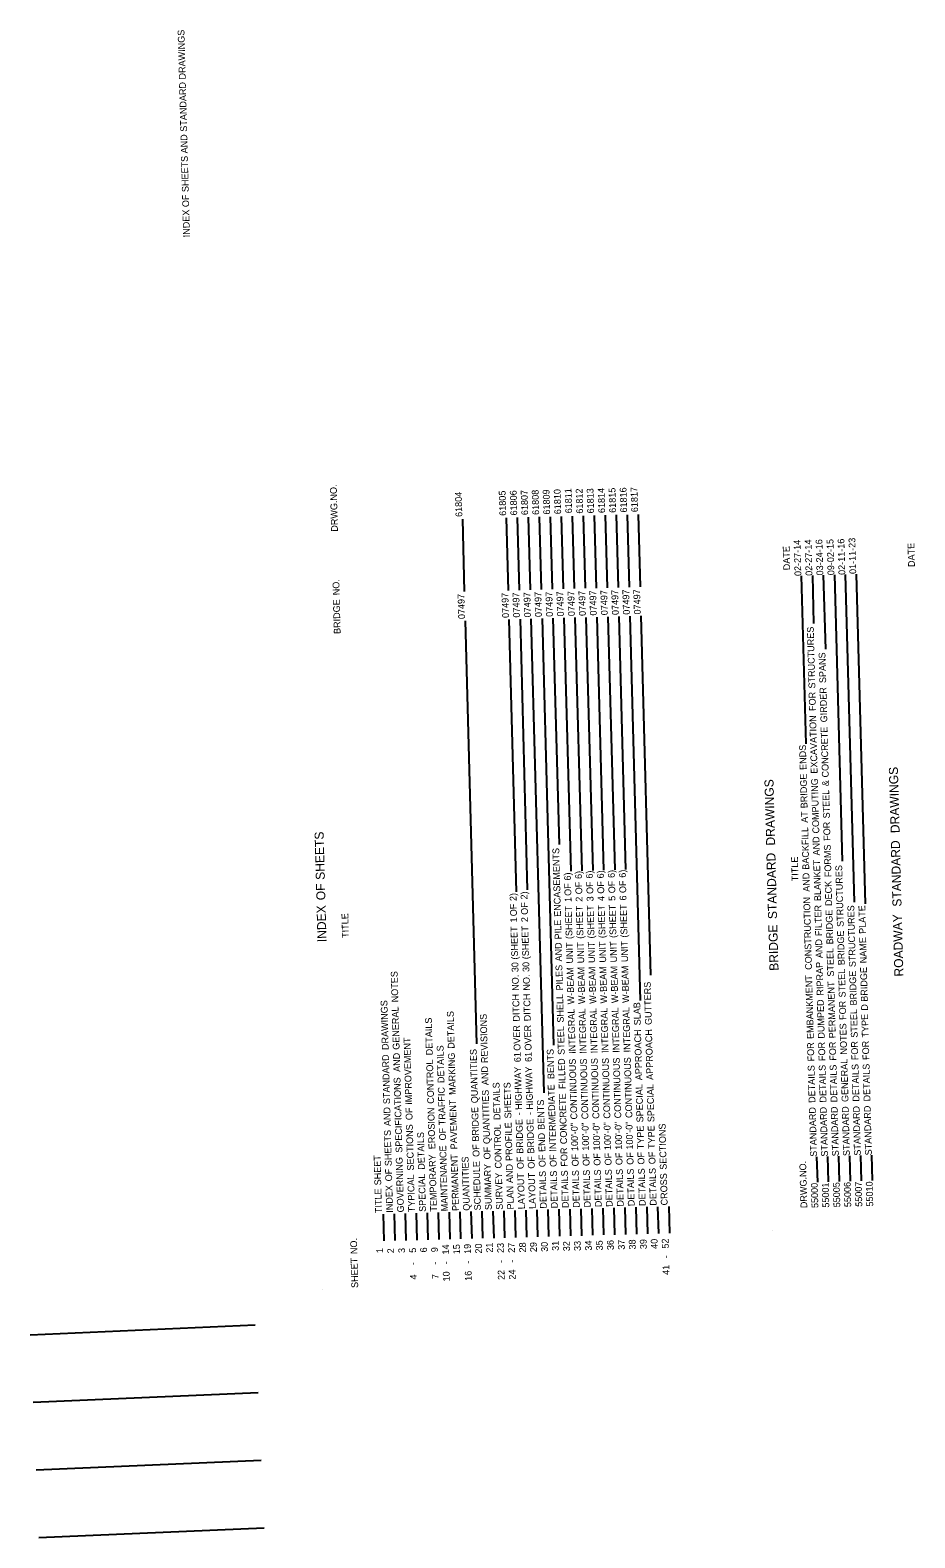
# Model space of a CAD drawing. Extents: x 1930579 to 1932146, y 596452 to 597806.
# Drawn here: x 1930579 to 1931365, y 596452 to 597789 of the extents above; entities that cross this region are included whole.
import ezdxf

# ---------------------------------------------------------------- set-up
doc = ezdxf.new("R2010")
doc.units = 0
for name, color, linetype in [('BR_Pr_Bent_CL', 7, 'Continuous'), ('Default', 7, 'Continuous'), ('R_Border', 7, 'Continuous')]:
    doc.layers.add(name, color=color, linetype=linetype)

msp = doc.modelspace()

# ---------------------------------------------------------------- linework, layer by layer
at = {"layer": 'BR_Pr_Bent_CL'}
for p, q in [((1930779.3, 596640.3), (1930579.5, 596631.6)), ((1930781.9, 596580.4), (1930582.1, 596571.7)), ((1930784.5, 596520.4), (1930584.7, 596511.8)), ((1930787.1, 596460.5), (1930587.3, 596451.8))]:
    msp.add_line(p, q, dxfattribs=at)
at = {"layer": 'Default'}
for p, q in [((1930963, 597355.3), (1930964.7, 597291)), ((1931002, 597356.4), (1931003.7, 597292)), ((1931011.7, 597356.6), (1931013.5, 597292.3)), ((1931021.5, 597356.9), (1931023.2, 597292.6)), ((1931031.2, 597357.2), (1931033, 597292.8)), ((1931041, 597357.4), (1931042.7, 597293.1)), ((1931050.7, 597357.7), (1931052.5, 597293.4)), ((1931060.5, 597357.9), (1931062.2, 597293.6)), ((1931070.2, 597358.2), (1931071.9, 597293.9)), ((1931080, 597358.5), (1931081.7, 597294.1)), ((1931089.7, 597358.7), (1931091.4, 597294.4)), ((1931099.5, 597359), (1931101.2, 597294.7)), ((1931109.2, 597359.2), (1931110.9, 597294.9)), ((1931119, 597359.5), (1931120.7, 597295.2)), ((1931263.8, 597305.1), (1931267.8, 597156.1)), ((1931273.6, 597305.4), (1931274.7, 597262.7)), ((1931283.3, 597305.7), (1931285.1, 597239.8)), ((1931293.1, 597305.9), (1931299.9, 597052)), ((1931302.8, 597306.2), (1931310.6, 597015.7)), ((1931312.5, 597306.4), (1931320.4, 597014.2)), ((1930965.4, 597265.2), (1930975.5, 596890)), ((1931004.4, 597266.3), (1931010.9, 597024.8)), ((1931014.2, 597266.6), (1931020.6, 597026.4)), ((1931023.9, 597266.8), (1931035.2, 596846.4)), ((1931033.7, 597267.1), (1931043.8, 596888.8)), ((1931043.4, 597267.3), (1931048.8, 597066.7)), ((1931053.1, 597267.6), (1931059.2, 597043.2)), ((1931062.9, 597267.9), (1931068.9, 597043.4)), ((1931072.6, 597268.1), (1931078.7, 597043.7)), ((1931082.4, 597268.4), (1931088.4, 597044)), ((1931092.1, 597268.6), (1931098.2, 597044.2)), ((1931101.9, 597268.9), (1931107.9, 597044.5)), ((1931111.6, 597269.2), (1931120.8, 596928.4)), ((1931121.4, 597269.4), (1931129.9, 596950.7)), ((1931278.3, 596767.3), (1931277.7, 596789.8)), ((1931288, 596767.5), (1931287.4, 596790)), ((1931297.7, 596767.8), (1931297.1, 596790.3)), ((1931307.5, 596768.1), (1931306.9, 596790.5)), ((1931317.2, 596768.3), (1931316.6, 596790.8)), ((1931327, 596768.6), (1931326.4, 596791.1)), ((1930893.6, 596715.1), (1930893, 596739)), ((1930903.4, 596715.4), (1930902.7, 596739.3)), ((1930913.1, 596715.6), (1930912.5, 596739.5)), ((1930922.9, 596715.9), (1930922.2, 596739.8)), ((1930932.6, 596716.2), (1930932, 596740)), ((1930942.3, 596716.4), (1930941.7, 596740.3)), ((1930952.1, 596716.7), (1930951.5, 596740.6)), ((1930961.8, 596717), (1930961.2, 596740.8)), ((1930971.6, 596717.2), (1930970.9, 596741.1)), ((1930981.3, 596717.5), (1930980.7, 596741.4)), ((1930991.1, 596717.7), (1930990.4, 596741.6)), ((1931000.8, 596718), (1931000.2, 596741.9)), ((1931010.6, 596718.3), (1931009.9, 596742.1)), ((1931020.3, 596718.5), (1931019.7, 596742.4)), ((1931030.1, 596718.8), (1931029.4, 596742.7)), ((1931039.8, 596719), (1931039.2, 596742.9)), ((1931049.6, 596719.3), (1931048.9, 596743.2)), ((1931059.3, 596719.6), (1931058.7, 596743.4)), ((1931069, 596719.8), (1931068.4, 596743.7)), ((1931078.8, 596720.1), (1931078.2, 596744)), ((1931088.5, 596720.4), (1931087.9, 596744.2)), ((1931098.3, 596720.6), (1931097.6, 596744.5)), ((1931108, 596720.9), (1931107.4, 596744.8)), ((1931117.8, 596721.1), (1931117.1, 596745)), ((1931127.5, 596721.4), (1931126.9, 596745.3)), ((1931137.3, 596721.7), (1931136.6, 596745.5)), ((1931147, 596721.9), (1931146.4, 596745.8)), ((1931238.2, 596724.3), (1931238.2, 596724.3)), ((1930839.2, 596671.7), (1930839.2, 596671.7))]:
    msp.add_line(p, q, dxfattribs=at)

# ---------------------------------------------------------------- texts
for s, height, p in [('DRWG.NO.', 6, (1930852.6, 597344.2)), ('61805', 6, (1931001.9, 597358.3)), ('61806', 6, (1931011.7, 597358.6)), ('61807', 6, (1931021.4, 597358.9)), ('61808', 6, (1931031.2, 597359.1)), ('61809', 6, (1931040.9, 597359.4)), ('61810', 6, (1931050.7, 597359.7)), ('61811', 6, (1931060.4, 597360.5)), ('61812', 6, (1931070.2, 597360.2)), ('61813', 6, (1931079.9, 597360.4)), ('61814', 6, (1931089.7, 597360.7)), ('61815', 6, (1931099.4, 597360.9)), ('61816', 6, (1931109.2, 597361.2)), ('61817', 6, (1931118.9, 597361.5)), ('61804', 6, (1930963, 597357.3)), ('DATE', 6, (1931253.9, 597310)), ('02-27-14', 6, (1931263.8, 597304.9)), ('02-27-14', 6, (1931273.6, 597305.1)), ('03-24-16', 6, (1931283.3, 597305.4)), ('09-02-15', 6, (1931293.1, 597305.6)), ('02-11-16', 6, (1931302.8, 597305.9)), ('01-11-23', 6, (1931312.5, 597306.7)), ('DATE', 6, (1931364.6, 597312.9)), (' NO.', 6, (1930854.2, 597285.6)), ('07497', 6, (1930965.4, 597266.7)), ('07497', 6, (1931004.4, 597267.7)), ('07497', 6, (1931014.1, 597268)), ('07497', 6, (1931023.9, 597268.2)), ('07497', 6, (1931033.6, 597268.5)), ('07497', 6, (1931043.4, 597268.7)), ('07497', 6, (1931053.1, 597269)), ('07497', 6, (1931062.9, 597269.3)), ('07497', 6, (1931072.6, 597269.5)), ('07497', 6, (1931082.3, 597269.8)), ('07497', 6, (1931092.1, 597270.1)), ('07497', 6, (1931101.8, 597270.3)), ('07497', 6, (1931111.6, 597270.6)), ('07497', 6, (1931121.3, 597270.8)), ('BRIDGE', 6, (1930855, 597253.5)), (' STRUCTURES', 6, (1931276.3, 597202.9)), (' SPANS', 6, (1931285.9, 597207.7)), (' FOR', 6, (1931276.8, 597183)), (' GIRDER', 6, (1931286.9, 597172.9)), (' EXCAVATION', 6, (1931278.3, 597127.4)), (' CONCRETE', 6, (1931288.2, 597124)), (' ENDS', 6, (1931268.5, 597130.7)), (' BRIDGE', 6, (1931269.4, 597096.7)), (' DRAWINGS', 8, (1931351.1, 597073.9)), (' DRAWINGS', 8, (1931240.7, 597062.9)), (' COMPUTING', 6, (1931279.8, 597074.3)), (' &', 6, (1931288.4, 597116.3)), (' STEEL', 6, (1931289.2, 597087.7)), (' AT', 6, (1931269.8, 597083.8)), (' FOR', 6, (1931289.7, 597067.8)), (' SHEETS', 8, (1930841.1, 597032.5)), (' BACKFILL', 6, (1931270.9, 597042.2)), (' AND', 6, (1931280.3, 597054.8)), (' ENCASEMENTS', 6, (1931050.6, 597000.4)), (' FORMS', 6, (1931290.6, 597035.6)), (' STANDARD', 8, (1931352.8, 597008.7)), (' STANDARD', 8, (1931242.4, 596997.7)), ('TITLE', 6, (1931261.3, 597034.2)), (' BLANKET', 6, (1931281.4, 597014.4)), (' STRUCTURES', 6, (1931301.5, 596991.5)), (' 6)', 6, (1931059.5, 597032.6)), (' 6)', 6, (1931069.2, 597034)), (' OF', 6, (1931069.5, 597020.4)), (' 6)', 6, (1931078.9, 597034.3)), (' OF', 6, (1931079.3, 597020.7)), (' 6)', 6, (1931088.7, 597034.5)), (' OF', 6, (1931089, 597020.9)), (' 6)', 6, (1931098.4, 597034.9)), (' OF', 6, (1931098.8, 597021.3)), (' 6)', 6, (1931108.2, 597035.1)), (' OF', 6, (1931108.5, 597021.5)), (' AND', 6, (1931271.4, 597022.6)), (' DECK', 6, (1931291.2, 597010)), (' OF', 8, (1930841.6, 597014.4)), (' 2)', 6, (1931011.2, 597014.4)), (' 2)', 6, (1931020.9, 597015.8)), (' OF', 6, (1931059.8, 597019)), (' 1', 6, (1931060, 597013.6)), (' 2', 6, (1931069.7, 597013.8)), (' 3', 6, (1931079.5, 597014.1)), (' 4', 6, (1931089.2, 597014.4)), (' 5', 6, (1931098.9, 597014.6)), (' 6', 6, (1931108.7, 597014.9)), (' CONSTRUCTION', 6, (1931273.3, 596953.4)), ('INDEX', 8, (1930842.5, 596980.2)), (' OF', 6, (1931011.5, 597000.9)), (' OF', 6, (1931021.3, 597002.2)), (' (SHEET', 6, (1931060.8, 596980.7)), (' (SHEET', 6, (1931070.6, 596980.9)), (' (SHEET', 6, (1931080.3, 596981.2)), (' (SHEET', 6, (1931090.1, 596981.5)), (' (SHEET', 6, (1931099.8, 596981.7)), (' (SHEET', 6, (1931109.6, 596982)), (' FILTER', 6, (1931282.2, 596983.3)), (' BRIDGE', 6, (1931292.2, 596976)), (' STRUCTURES', 6, (1931312.2, 596955.8)), (' PLATE', 6, (1931321.2, 596985.3)), ('TITLE', 6, (1930862.3, 596984)), (' 1', 6, (1931011.7, 596995.4)), (' (SHEET', 6, (1931012.6, 596962.5)), (' 2', 6, (1931021.4, 596995.7)), (' (SHEET', 6, (1931022.3, 596962.8)), (' PILE', 6, (1931051.1, 596980.4)), ('BRIDGE', 8, (1931243.6, 596954.8)), ('ROADWAY', 8, (1931354.4, 596949.7)), (' AND', 6, (1931051.6, 596960.8)), (' UNIT', 6, (1931061.4, 596959)), (' UNIT', 6, (1931071.2, 596959.2)), (' UNIT', 6, (1931080.9, 596959.5)), (' UNIT', 6, (1931090.7, 596959.8)), (' UNIT', 6, (1931100.4, 596960)), (' UNIT', 6, (1931110.2, 596960.3)), (' AND', 6, (1931282.7, 596963.8)), (' BRIDGE', 6, (1931302.4, 596957.5)), (' NAME', 6, (1931321.9, 596959.2)), (' STEEL', 6, (1931292.9, 596947.4)), (' NOTES', 6, (1930906.3, 596924.6)), (' 30', 6, (1931012.9, 596951.3)), (' 30', 6, (1931022.6, 596951.5)), (' PILES', 6, (1931052.3, 596935.1)), (' W-BEAM', 6, (1931062.4, 596922.8)), (' W-BEAM', 6, (1931072.1, 596923.1)), (' W-BEAM', 6, (1931081.9, 596923.3)), (' W-BEAM', 6, (1931091.6, 596923.6)), (' W-BEAM', 6, (1931101.4, 596923.9)), (' W-BEAM', 6, (1931111.1, 596924.1)), (' RIPRAP', 6, (1931283.6, 596930.6)), (' STEEL', 6, (1931303.2, 596928.9)), (' BRIDGE', 6, (1931313.1, 596921.8)), (' BRIDGE', 6, (1931322.8, 596925.1)), (' NO.', 6, (1931013.3, 596934.8)), (' NO.', 6, (1931023.1, 596935)), (' GUTTERS', 6, (1931131.2, 596904.5)), (' EMBANKMENT', 6, (1931274.9, 596892.1)), (' PERMANENT', 6, (1931294.4, 596892.7)), (' DRAWINGS', 6, (1930897.7, 596882.3)), (' DITCH', 6, (1931014, 596907.5)), (' DITCH', 6, (1931023.8, 596907.8)), (' SHELL', 6, (1931053.1, 596906.6)), (' SLAB', 6, (1931121.4, 596904.2)), (' DUMPED', 6, (1931284.6, 596892.4)), (' FOR', 6, (1931303.7, 596909)), (' GENERAL', 6, (1930907.4, 596882.5)), (' DETAILS', 6, (1930936.8, 596877.6)), (' DETAILS', 6, (1930956.2, 596883.4)), (' REVISIONS', 6, (1930985.8, 596870.7)), (' INTEGRAL', 6, (1931063.6, 596878.9)), (' INTEGRAL', 6, (1931073.3, 596879.1)), (' INTEGRAL', 6, (1931083.1, 596879.4)), (' INTEGRAL', 6, (1931092.8, 596879.7)), (' INTEGRAL', 6, (1931102.6, 596879.9)), (' INTEGRAL', 6, (1931112.3, 596880.2)), (' STEEL', 6, (1931313.9, 596893.2)), (' D', 6, (1931323, 596917.2)), (' TYPE', 6, (1931323.6, 596893.4)), (' OVER', 6, (1931014.7, 596881.6)), (' OVER', 6, (1931024.5, 596881.8)), (' STEEL', 6, (1931053.9, 596878)), (' APPROACH', 6, (1931122.7, 596855.5)), (' APPROACH', 6, (1931132.5, 596855.8)), (' NOTES', 6, (1931304.5, 596878.3)), (' IMPROVEMENT', 6, (1930918.5, 596833.7)), (' DETAILS', 6, (1930947.2, 596853)), (' FOR', 6, (1931275.4, 596872.2)), (' FOR', 6, (1931285.2, 596872.5)), (' FOR', 6, (1931294.9, 596872.8)), (' FOR', 6, (1931314.4, 596873.3)), (' FOR', 6, (1931324.2, 596873.5)), (' STANDARD', 6, (1930899, 596834.3)), (' AND', 6, (1930908, 596862.9)), (' CONTROL', 6, (1930938, 596834.6)), (' MARKING', 6, (1930957.3, 596842.5)), (' QUANTITIES', 6, (1930977, 596835.1)), (' 61', 6, (1931015, 596871.5)), (' 61', 6, (1931024.8, 596871.7)), (' BENTS', 6, (1931044.7, 596856.5)), (' FILLED', 6, (1931054.7, 596847.7)), (' CONTINUOUS', 6, (1931065.1, 596820.7)), (' CONTINUOUS', 6, (1931074.9, 596820.9)), (' CONTINUOUS', 6, (1931084.6, 596821.2)), (' CONTINUOUS', 6, (1931094.4, 596821.4)), (' CONTINUOUS', 6, (1931104.1, 596821.7)), (' CONTINUOUS', 6, (1931113.9, 596822)), (' GENERAL', 6, (1931305.7, 596836.2)), (' DETAILS', 6, (1931325.2, 596836.7)), (' SPECIFICATIONS', 6, (1930909.9, 596791.2)), (' AND', 6, (1930986.3, 596851.1)), (' HIGHWAY', 6, (1931016.1, 596829.2)), (' HIGHWAY', 6, (1931025.9, 596829.4)), (' DETAILS', 6, (1931276.4, 596835.4)), (' DETAILS', 6, (1931286.2, 596835.7)), (' DETAILS', 6, (1931295.9, 596835.9)), (' DETAILS', 6, (1931315.4, 596836.5)), (' TRAFFIC', 6, (1930948.2, 596815.6)), (' QUANTITIES', 6, (1930987.7, 596798.9)), (' DETAILS', 6, (1930996.9, 596820.2)), (' SHEETS', 6, (1931006.6, 596821.6)), (' INTERMEDIATE', 6, (1931046.4, 596792.2)), (' CONCRETE', 6, (1931056, 596798.8)), (' SPECIAL', 6, (1931123.7, 596818.1)), (' SPECIAL', 6, (1931133.5, 596818.3)), (' AND', 6, (1930899.5, 596814.8)), (' OF', 6, (1930918.9, 596820.1)), (' EROSION', 6, (1930939.1, 596794.3)), (' PAVEMENT', 6, (1930958.6, 596794.2)), (' BRIDGE', 6, (1930977.9, 596801.1)), (' BENTS', 6, (1931036.1, 596811.5)), ('STANDARD', 6, (1931277.7, 596789.8)), ('STANDARD', 6, (1931287.4, 596790)), ('STANDARD', 6, (1931297.1, 596790.3)), ('STANDARD', 6, (1931306.9, 596790.5)), ('STANDARD', 6, (1931316.6, 596790.8)), ('STANDARD', 6, (1931326.4, 596791.1)), (' CONTROL', 6, (1930998, 596777.2)), (' PROFILE', 6, (1931007.6, 596783.9)), (' BRIDGE', 6, (1931017.2, 596790.3)), (' -', 6, (1931016.3, 596824.3)), (' BRIDGE', 6, (1931026.9, 596790.5)), (' -', 6, (1931026, 596824.6)), (' 100\'-0"', 6, (1931065.9, 596792.7)), (' 100\'-0"', 6, (1931075.6, 596793)), (' 100\'-0"', 6, (1931085.4, 596793.2)), (' 100\'-0"', 6, (1931095.1, 596793.5)), (' 100\'-0"', 6, (1931104.9, 596793.8)), (' 100\'-0"', 6, (1931114.6, 596794)), (' SECTIONS', 6, (1931144.4, 596776.1)), (' SHEETS', 6, (1930900.4, 596779.3)), (' SECTIONS', 6, (1930920.1, 596775.4)), (' DETAILS', 6, (1930929.8, 596776.1)), (' OF', 6, (1930948.6, 596802.1)), (' END', 6, (1931036.7, 596791.9)), (' TYPE', 6, (1931124.4, 596794.3)), (' TYPE', 6, (1931134.1, 596794.6)), ('TEMPORARY', 6, (1930940.5, 596741.2)), ('MAINTENANCE', 6, (1930950.2, 596741.5)), ('PERMANENT', 6, (1930960, 596741.8)), (' OF', 6, (1930978.3, 596787.5)), (' OF', 6, (1930988.1, 596785.3)), (' FOR', 6, (1931056.5, 596778.9)), (' OF', 6, (1931066.3, 596779.1)), (' OF', 6, (1931076, 596779.4)), (' OF', 6, (1931085.7, 596779.7)), (' OF', 6, (1931095.5, 596779.9)), (' OF', 6, (1931105.2, 596780.2)), (' OF', 6, (1931115, 596780.5)), (' OF', 6, (1931124.7, 596780.7)), (' OF', 6, (1931134.5, 596781)), (' SHEET', 6, (1930891.1, 596762.3)), (' OF', 6, (1930900.8, 596765.8)), ('GOVERNING', 6, (1930911.2, 596740.5)), ('QUANTITIES', 6, (1930969.7, 596742)), ('SCHEDULE', 6, (1930979.5, 596742.3)), ('SUMMARY', 6, (1930989.2, 596742.6)), (' AND', 6, (1931008.1, 596764.3)), (' OF', 6, (1931017.6, 596776.7)), (' OF', 6, (1931027.3, 596777)), (' OF', 6, (1931037, 596778.4)), (' OF', 6, (1931046.8, 596778.6)), ('DETAILS', 6, (1931096.4, 596745.4)), ('DETAILS', 6, (1931106.2, 596745.7)), ('DETAILS', 6, (1931115.9, 596746)), ('DETAILS', 6, (1931125.7, 596746.2)), ('DETAILS', 6, (1931135.4, 596746.5)), ('DRWG.NO.', 6, (1931269.1, 596744.3)), ('TYPICAL', 6, (1930921, 596740.7)), ('SPECIAL', 6, (1930930.7, 596741)), ('SURVEY', 6, (1930999, 596742.8)), ('LAYOUT', 6, (1931018.5, 596743.3)), ('LAYOUT', 6, (1931028.2, 596743.6)), ('DETAILS', 6, (1931037.9, 596743.9)), ('DETAILS', 6, (1931047.7, 596744.1)), ('DETAILS', 6, (1931057.4, 596744.4)), ('DETAILS', 6, (1931067.2, 596744.6)), ('DETAILS', 6, (1931076.9, 596744.9)), ('DETAILS', 6, (1931086.7, 596745.2)), ('CROSS', 6, (1931145.2, 596746.7)), ('55000', 6, (1931278.9, 596744.4)), ('55001', 6, (1931288.6, 596744.7)), ('55005', 6, (1931298.4, 596745)), ('55006', 6, (1931308.1, 596745.2)), ('55007', 6, (1931317.9, 596745.5)), ('55010', 6, (1931327.6, 596745.7)), ('TITLE', 6, (1930891.7, 596739.9)), ('INDEX', 6, (1930901.5, 596740.2)), ('PLAN', 6, (1931008.7, 596743.1)), (' NO.', 6, (1930869.9, 596701.3)), ('14', 6, (1930951.3, 596703.2)), ('15', 6, (1930961, 596703.4)), ('19', 6, (1930970.7, 596703.7)), ('20', 6, (1930980.5, 596704)), ('21', 6, (1930990.2, 596704.8)), ('23', 6, (1931000, 596704.5)), ('27', 6, (1931009.7, 596704.7)), ('28', 6, (1931019.5, 596705)), ('29', 6, (1931029.2, 596705.3)), ('30', 6, (1931039, 596705.5)), ('31', 6, (1931048.7, 596706.4)), ('32', 6, (1931058.5, 596706.1)), ('33', 6, (1931068.2, 596706.3)), ('34', 6, (1931078, 596706.6)), ('35', 6, (1931087.7, 596706.8)), ('36', 6, (1931097.5, 596707.1)), ('37', 6, (1931107.2, 596707.4)), ('38', 6, (1931116.9, 596707.6)), ('39', 6, (1931126.7, 596707.9)), ('40', 6, (1931136.4, 596708.2)), ('52', 6, (1931146.2, 596708.4)), ('SHEET', 6, (1930870.6, 596673.5)), ('1', 6, (1930892.7, 596704.5)), ('2', 6, (1930902.5, 596704.2)), ('3', 6, (1930912.2, 596704.5)), ('5', 6, (1930922, 596704.7)), ('6', 6, (1930931.7, 596705)), ('9', 6, (1930941.4, 596705.2)), ('-', 6, (1931010, 596696)), ('-', 6, (1931146.4, 596699.7)), ('4', 6, (1930922.6, 596680.9)), ('-', 6, (1930922.2, 596693.7)), ('7', 6, (1930942.1, 596681.4)), ('-', 6, (1930941.7, 596694.2)), ('10', 6, (1930951.9, 596679.3)), ('-', 6, (1930951.5, 596694.4)), ('16', 6, (1930971.4, 596679.8)), ('-', 6, (1930971, 596695)), ('22', 6, (1931000.6, 596680.6)), ('-', 6, (1931000.2, 596695.7)), ('24', 6, (1931010.4, 596680.9)), ('41', 6, (1931146.8, 596685.1))]:
    msp.add_text(s, height=height, rotation=91.5377, dxfattribs=at).set_placement(p)
at = {"layer": 'R_Border'}
msp.add_text('INDEX OF SHEETS AND STANDARD DRAWINGS', height=6, rotation=91.5377, dxfattribs=at).set_placement((1930721.3, 597605.3))

doc.saveas('drawing.dxf')
